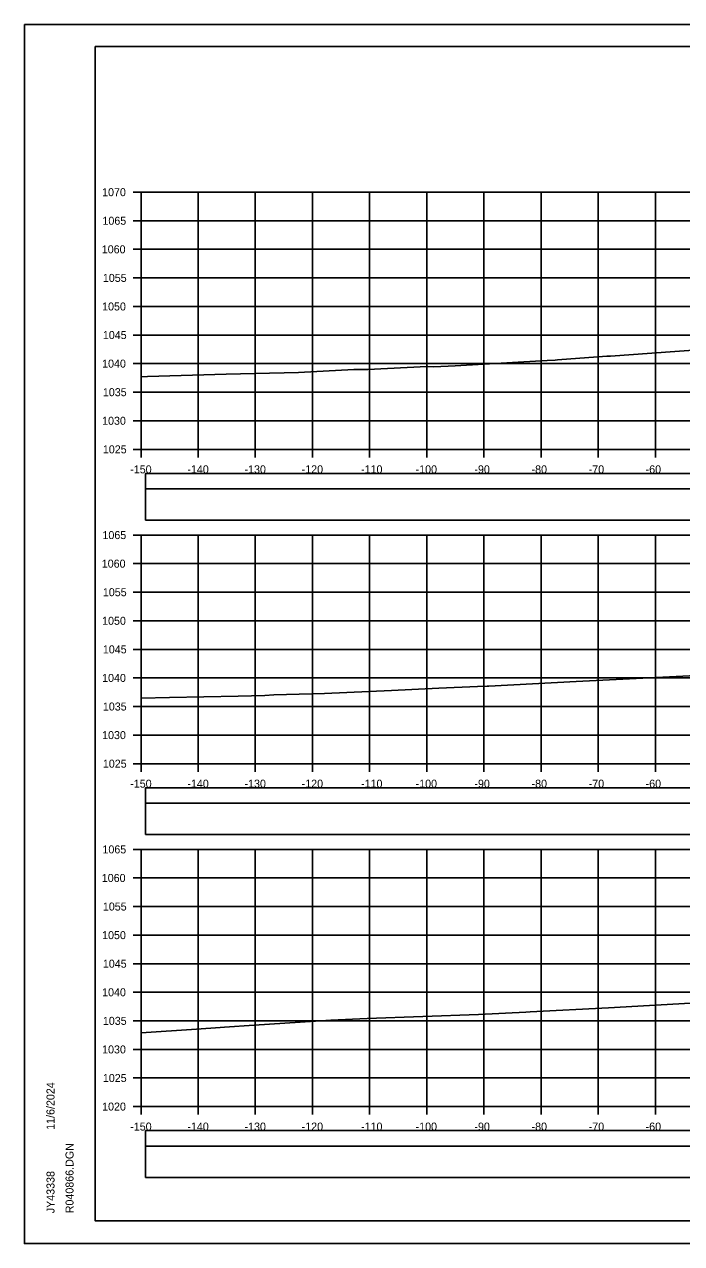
# Model space of a CAD drawing. Extents: x 1370565 to 1374448, y 301010 to 304637.
# Drawn here: x 1370564.6 to 1370679.6, y 303357.2 to 303570.5 of the extents above; entities that cross this region are included whole.
import ezdxf

# ---------------------------------------------------------------- set-up
doc = ezdxf.new("R2010")
doc.units = 0
for name, color, linetype in [('Default', 7, 'Continuous'), ('R_Axis', 7, 'Continuous'), ('R_Axis Annot', 7, 'Continuous'), ('R_Border', 7, 'Continuous'), ('R_Drive', 7, 'Continuous'), ('R_Exist Surface', 7, 'Continuous'), ('R_Grid', 7, 'Continuous'), ('R_No Plot', 7, 'Continuous')]:
    doc.layers.add(name, color=color, linetype=linetype)

msp = doc.modelspace()

# ---------------------------------------------------------------- linework, layer by layer
at = {"layer": 'Default'}
msp.add_lwpolyline([(1370585.82, 303368.77), (1370884.24, 303368.77), (1370884.24, 303374.29), (1370585.82, 303374.29)], close=True, dxfattribs=at)
at = {"layer": 'R_Axis'}
for p, q in [((1370583.63, 303541.19), (1370585.03, 303541.19)), ((1370585.03, 303496.19), (1370585.03, 303541.19)), ((1370583.63, 303536.19), (1370585.03, 303536.19)), ((1370583.63, 303531.19), (1370585.03, 303531.19)), ((1370583.63, 303526.19), (1370585.03, 303526.19)), ((1370583.63, 303521.19), (1370585.03, 303521.19)), ((1370583.63, 303516.19), (1370585.03, 303516.19)), ((1370583.63, 303511.19), (1370585.03, 303511.19)), ((1370583.63, 303506.19), (1370585.03, 303506.19)), ((1370583.63, 303501.19), (1370585.03, 303501.19)), ((1370583.63, 303496.19), (1370585.03, 303496.19)), ((1370585.03, 303496.19), (1370885.03, 303496.19)), ((1370585.03, 303494.79), (1370585.03, 303496.19)), ((1370595.03, 303494.79), (1370595.03, 303496.19)), ((1370605.03, 303494.79), (1370605.03, 303496.19)), ((1370615.03, 303494.79), (1370615.03, 303496.19)), ((1370625.03, 303494.79), (1370625.03, 303496.19)), ((1370635.03, 303494.79), (1370635.03, 303496.19)), ((1370645.03, 303494.79), (1370645.03, 303496.19)), ((1370655.03, 303494.79), (1370655.03, 303496.19)), ((1370665.03, 303494.79), (1370665.03, 303496.19)), ((1370675.03, 303494.79), (1370675.03, 303496.19)), ((1370583.63, 303481.19), (1370585.03, 303481.19)), ((1370585.03, 303441.19), (1370585.03, 303481.19)), ((1370583.63, 303476.19), (1370585.03, 303476.19)), ((1370583.63, 303471.19), (1370585.03, 303471.19)), ((1370583.63, 303466.19), (1370585.03, 303466.19)), ((1370583.63, 303461.19), (1370585.03, 303461.19)), ((1370583.63, 303456.19), (1370585.03, 303456.19)), ((1370583.63, 303451.19), (1370585.03, 303451.19)), ((1370583.63, 303446.19), (1370585.03, 303446.19)), ((1370583.63, 303441.19), (1370585.03, 303441.19)), ((1370585.03, 303441.19), (1370885.03, 303441.19)), ((1370585.03, 303439.79), (1370585.03, 303441.19)), ((1370595.03, 303439.79), (1370595.03, 303441.19)), ((1370605.03, 303439.79), (1370605.03, 303441.19)), ((1370615.03, 303439.79), (1370615.03, 303441.19)), ((1370625.03, 303439.79), (1370625.03, 303441.19)), ((1370635.03, 303439.79), (1370635.03, 303441.19)), ((1370645.03, 303439.79), (1370645.03, 303441.19)), ((1370655.03, 303439.79), (1370655.03, 303441.19)), ((1370665.03, 303439.79), (1370665.03, 303441.19)), ((1370675.03, 303439.79), (1370675.03, 303441.19)), ((1370583.63, 303426.19), (1370585.03, 303426.19)), ((1370585.03, 303381.19), (1370585.03, 303426.19)), ((1370583.63, 303421.19), (1370585.03, 303421.19)), ((1370583.63, 303416.19), (1370585.03, 303416.19)), ((1370583.63, 303411.19), (1370585.03, 303411.19)), ((1370583.63, 303406.19), (1370585.03, 303406.19)), ((1370583.63, 303401.19), (1370585.03, 303401.19)), ((1370583.63, 303396.19), (1370585.03, 303396.19)), ((1370583.63, 303391.19), (1370585.03, 303391.19)), ((1370583.63, 303386.19), (1370585.03, 303386.19)), ((1370583.63, 303381.19), (1370585.03, 303381.19)), ((1370585.03, 303381.19), (1370885.03, 303381.19)), ((1370585.03, 303379.79), (1370585.03, 303381.19)), ((1370595.03, 303379.79), (1370595.03, 303381.19)), ((1370605.03, 303379.79), (1370605.03, 303381.19)), ((1370615.03, 303379.79), (1370615.03, 303381.19)), ((1370625.03, 303379.79), (1370625.03, 303381.19)), ((1370635.03, 303379.79), (1370635.03, 303381.19)), ((1370645.03, 303379.79), (1370645.03, 303381.19)), ((1370655.03, 303379.79), (1370655.03, 303381.19)), ((1370665.03, 303379.79), (1370665.03, 303381.19)), ((1370675.03, 303379.79), (1370675.03, 303381.19))]:
    msp.add_line(p, q, dxfattribs=at)
at = {"layer": 'R_Border'}
for p, q in [((1370577.03, 303566.65), (1370893.21, 303566.65)), ((1370577.03, 303361.19), (1370577.03, 303566.65)), ((1370577.03, 303361.19), (1370577.03, 303361.19)), ((1370893.21, 303361.19), (1370577.03, 303361.19))]:
    msp.add_line(p, q, dxfattribs=at)
at = {"layer": 'R_Drive'}
for points in [[(1370585.82, 303489.29), (1370884.24, 303489.29), (1370884.24, 303491.99), (1370585.82, 303491.99)], [(1370585.82, 303483.77), (1370884.24, 303483.77), (1370884.24, 303489.29), (1370585.82, 303489.29)], [(1370585.82, 303434.29), (1370884.24, 303434.29), (1370884.24, 303436.99), (1370585.82, 303436.99)], [(1370585.82, 303428.77), (1370884.24, 303428.77), (1370884.24, 303434.29), (1370585.82, 303434.29)], [(1370585.82, 303374.29), (1370884.24, 303374.29), (1370884.24, 303376.99), (1370585.82, 303376.99)]]:
    msp.add_lwpolyline(points, close=True, dxfattribs=at)
at = {"layer": 'R_Exist Surface'}
for points in [[(1370585.03, 303508.9), (1370586.18, 303508.94), (1370599.95, 303509.32), (1370612.58, 303509.61), (1370622.28, 303510.17), (1370624.74, 303510.18), (1370635.07, 303510.66), (1370635.18, 303510.66), (1370635.2, 303510.66), (1370636.26, 303510.63), (1370639.99, 303510.82), (1370655.04, 303511.67), (1370656.12, 303511.73), (1370657.51, 303511.81), (1370657.92, 303511.84), (1370666.55, 303512.47), (1370667.19, 303512.51), (1370674.44, 303513.04), (1370701.83, 303515)], [(1370585.03, 303452.63), (1370590.04, 303452.78), (1370602.03, 303453), (1370606.68, 303453.14), (1370608.26, 303453.21), (1370617.12, 303453.48), (1370628.89, 303454.02), (1370637.17, 303454.38), (1370643.91, 303454.67), (1370645.6, 303454.75), (1370645.92, 303454.77), (1370661.15, 303455.55), (1370682.19, 303456.63)], [(1370585.03, 303394.08), (1370594.71, 303394.72), (1370598.88, 303395.02), (1370599.64, 303395.06), (1370604.81, 303395.41), (1370618.27, 303396.33), (1370624.62, 303396.6), (1370644.1, 303397.31), (1370652.36, 303397.71), (1370653.1, 303397.74), (1370666.81, 303398.48), (1370685.28, 303399.5)]]:
    msp.add_lwpolyline(points, dxfattribs=at)
at = {"layer": 'R_Grid'}
for p, q in [((1370585.03, 303541.19), (1370885.03, 303541.19)), ((1370585.03, 303496.19), (1370585.03, 303541.19)), ((1370595.03, 303496.19), (1370595.03, 303541.19)), ((1370605.03, 303496.19), (1370605.03, 303541.19)), ((1370615.03, 303496.19), (1370615.03, 303541.19)), ((1370625.03, 303496.19), (1370625.03, 303541.19)), ((1370635.03, 303496.19), (1370635.03, 303541.19)), ((1370645.03, 303496.19), (1370645.03, 303541.19)), ((1370655.03, 303496.19), (1370655.03, 303541.19)), ((1370665.03, 303496.19), (1370665.03, 303541.19)), ((1370675.03, 303496.19), (1370675.03, 303541.19)), ((1370585.03, 303536.19), (1370885.03, 303536.19)), ((1370585.03, 303531.19), (1370885.03, 303531.19)), ((1370585.03, 303526.19), (1370885.03, 303526.19)), ((1370585.03, 303521.19), (1370885.03, 303521.19)), ((1370585.03, 303516.19), (1370885.03, 303516.19)), ((1370585.03, 303511.19), (1370885.03, 303511.19)), ((1370585.03, 303506.19), (1370885.03, 303506.19)), ((1370585.03, 303501.19), (1370885.03, 303501.19)), ((1370585.03, 303496.19), (1370885.03, 303496.19)), ((1370585.03, 303481.19), (1370885.03, 303481.19)), ((1370585.03, 303441.19), (1370585.03, 303481.19)), ((1370595.03, 303441.19), (1370595.03, 303481.19)), ((1370605.03, 303441.19), (1370605.03, 303481.19)), ((1370615.03, 303441.19), (1370615.03, 303481.19)), ((1370625.03, 303441.19), (1370625.03, 303481.19)), ((1370635.03, 303441.19), (1370635.03, 303481.19)), ((1370645.03, 303441.19), (1370645.03, 303481.19)), ((1370655.03, 303441.19), (1370655.03, 303481.19)), ((1370665.03, 303441.19), (1370665.03, 303481.19)), ((1370675.03, 303441.19), (1370675.03, 303481.19)), ((1370585.03, 303476.19), (1370885.03, 303476.19)), ((1370585.03, 303471.19), (1370885.03, 303471.19)), ((1370585.03, 303466.19), (1370885.03, 303466.19)), ((1370585.03, 303461.19), (1370885.03, 303461.19)), ((1370585.03, 303456.19), (1370885.03, 303456.19)), ((1370585.03, 303451.19), (1370885.03, 303451.19)), ((1370585.03, 303446.19), (1370885.03, 303446.19)), ((1370585.03, 303441.19), (1370885.03, 303441.19)), ((1370585.03, 303426.19), (1370885.03, 303426.19)), ((1370585.03, 303381.19), (1370585.03, 303426.19)), ((1370595.03, 303381.19), (1370595.03, 303426.19)), ((1370605.03, 303381.19), (1370605.03, 303426.19)), ((1370615.03, 303381.19), (1370615.03, 303426.19)), ((1370625.03, 303381.19), (1370625.03, 303426.19)), ((1370635.03, 303381.19), (1370635.03, 303426.19)), ((1370645.03, 303381.19), (1370645.03, 303426.19)), ((1370655.03, 303381.19), (1370655.03, 303426.19)), ((1370665.03, 303381.19), (1370665.03, 303426.19)), ((1370675.03, 303381.19), (1370675.03, 303426.19)), ((1370585.03, 303421.19), (1370885.03, 303421.19)), ((1370585.03, 303416.19), (1370885.03, 303416.19)), ((1370585.03, 303411.19), (1370885.03, 303411.19)), ((1370585.03, 303406.19), (1370885.03, 303406.19)), ((1370585.03, 303401.19), (1370885.03, 303401.19)), ((1370585.03, 303396.19), (1370885.03, 303396.19)), ((1370585.03, 303391.19), (1370885.03, 303391.19)), ((1370585.03, 303386.19), (1370885.03, 303386.19)), ((1370585.03, 303381.19), (1370885.03, 303381.19))]:
    msp.add_line(p, q, dxfattribs=at)
at = {"layer": 'R_No Plot'}
for p, q in [((1370564.63, 303570.55), (1370897.96, 303570.55)), ((1370564.63, 303357.22), (1370897.96, 303357.22))]:
    msp.add_line(p, q, dxfattribs=at)
for points in [[(1370564.62, 303570.55), (1370897.96, 303570.55), (1370897.96, 303357.21), (1370564.62, 303357.21)], [(1370810.95, 303566.65), (1370830.57, 303566.65), (1370830.57, 303556.77), (1370846.68, 303556.77), (1370869.88, 303556.77), (1370869.88, 303524.1), (1370893.09, 303524.1), (1370893.21, 303361.19), (1370577.03, 303361.19), (1370577.03, 303566.65)]]:
    msp.add_lwpolyline(points, close=True, dxfattribs=at)

# ---------------------------------------------------------------- texts
at = {"layer": 'R_Axis Annot'}
for s, p in [('1070', (1370578.22, 303540.49)), ('1065', (1370578.28, 303535.49)), ('1060', (1370578.16, 303530.49)), ('1055', (1370578.35, 303525.49)), ('1050', (1370578.22, 303520.49)), ('1045', (1370578.35, 303515.49)), ('1040', (1370578.22, 303510.49)), ('1035', (1370578.35, 303505.49)), ('1030', (1370578.22, 303500.49)), ('1025', (1370578.35, 303495.49)), ('-150', (1370583.14, 303491.99)), ('-140', (1370593.14, 303491.99)), ('-130', (1370603.14, 303491.99)), ('-120', (1370613.14, 303491.99)), ('-110', (1370623.53, 303491.99)), ('-100', (1370633.08, 303491.99)), ('-90', (1370643.37, 303491.99)), ('-80', (1370653.37, 303491.99)), ('-70', (1370663.37, 303491.99)), ('-60', (1370673.33, 303491.99)), ('1065', (1370578.28, 303480.49)), ('1060', (1370578.16, 303475.49)), ('1055', (1370578.35, 303470.49)), ('1050', (1370578.22, 303465.49)), ('1045', (1370578.35, 303460.49)), ('1040', (1370578.22, 303455.49)), ('1035', (1370578.35, 303450.49)), ('1030', (1370578.22, 303445.49)), ('1025', (1370578.35, 303440.49)), ('-150', (1370583.14, 303436.99)), ('-140', (1370593.14, 303436.99)), ('-130', (1370603.14, 303436.99)), ('-120', (1370613.14, 303436.99)), ('-110', (1370623.53, 303436.99)), ('-100', (1370633.08, 303436.99)), ('-90', (1370643.37, 303436.99)), ('-80', (1370653.37, 303436.99)), ('-70', (1370663.37, 303436.99)), ('-60', (1370673.33, 303436.99)), ('1065', (1370578.28, 303425.49)), ('1060', (1370578.16, 303420.49)), ('1055', (1370578.35, 303415.49)), ('1050', (1370578.22, 303410.49)), ('1045', (1370578.35, 303405.49)), ('1040', (1370578.22, 303400.49)), ('1035', (1370578.35, 303395.49)), ('1030', (1370578.22, 303390.49)), ('1025', (1370578.35, 303385.49)), ('1020', (1370578.22, 303380.49)), ('-150', (1370583.14, 303376.99)), ('-140', (1370593.14, 303376.99)), ('-130', (1370603.14, 303376.99)), ('-120', (1370613.14, 303376.99)), ('-110', (1370623.53, 303376.99)), ('-100', (1370633.08, 303376.99)), ('-90', (1370643.37, 303376.99)), ('-80', (1370653.37, 303376.99)), ('-70', (1370663.37, 303376.99)), ('-60', (1370673.33, 303376.99))]:
    msp.add_text(s, height=1.4, dxfattribs=at).set_placement(p)
at = {"layer": 'R_Border'}
for s, p in [('11/6/2024', (1370569.89, 303377.12)), ('R040866.DGN', (1370573.22, 303362.52)), ('JY43338', (1370569.89, 303362.52))]:
    msp.add_text(s, height=1.4, rotation=90, dxfattribs=at).set_placement(p)

doc.saveas('drawing.dxf')
